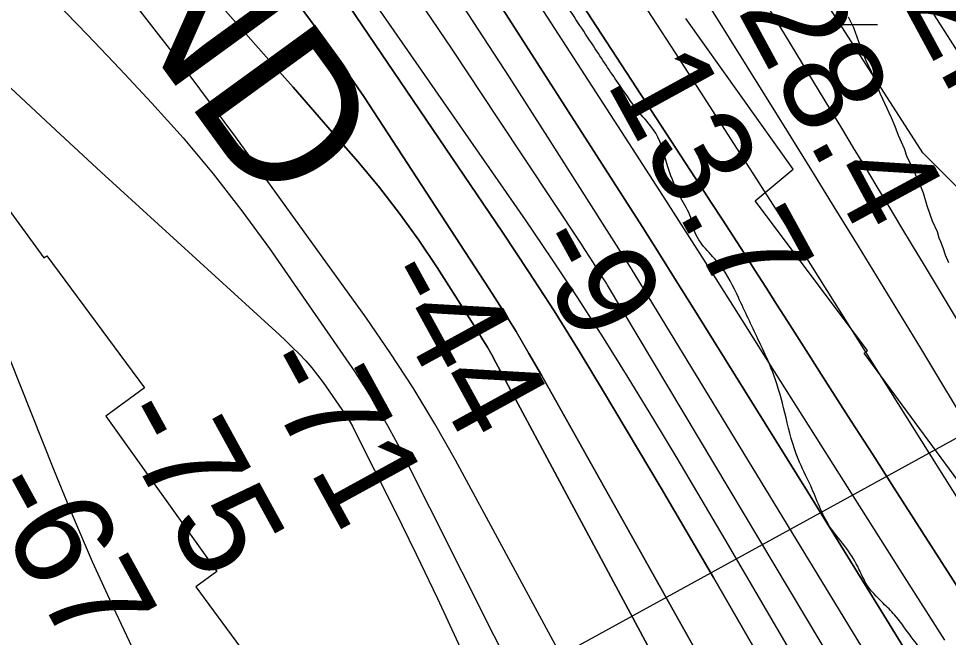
# Model space of a CAD drawing. Extents: x 3329297 to 3367176, y 649250 to 674653.
# Drawn here: x 3341150 to 3341775, y 667097 to 667513 of the extents above; entities that cross this region are included whole.
import ezdxf

# ---------------------------------------------------------------- set-up
doc = ezdxf.new("R2010")
doc.units = 0
for name, color, linetype in [('V-RIVR-EDGE', 7, 'Continuous'), ('V-RIVR-RANG', 7, 'Continuous'), ('V-RRAP-RVMT', 7, 'Continuous'), ('V-RRAP-RVMT-IDEN', 7, 'Continuous'), ('V-SITE-VEGE', 7, 'Continuous'), ('V-TOPO-DPTH', 7, 'Continuous'), ('V-TOPO-MAJR', 7, 'Continuous'), ('V-TOPO-MINR', 7, 'Continuous'), ('V-TOPO-WATR', 7, 'Continuous'), ('V-WETL-SWMP', 7, 'Continuous')]:
    doc.layers.add(name, color=color, linetype=linetype)

msp = doc.modelspace()

# ---------------------------------------------------------------- linework, layer by layer
at = {"layer": 'V-RIVR-EDGE'}
msp.add_spline([(3342816.41, 664076.7), (3342812.76, 664100.73), (3342811.24, 664114.69), (3342810.49, 664125.17), (3342811.67, 664129.43), (3342815.94, 664131.36), (3342822.14, 664130.96), (3342827.58, 664133.66), (3342827.98, 664138.7), (3342825.71, 664163.52), (3342823.01, 664169.35), (3342818.01, 664185.26), (3342816.5, 664200), (3342816.91, 664208.92), (3342818.1, 664220.94), (3342817.34, 664227.14), (3342814.66, 664243.44), (3342809.27, 664257.41), (3342808.51, 664264.01), (3342808.92, 664272.54), (3342814.79, 664296.18), (3342814.82, 664305.49), (3342810.59, 664319.46), (3342799.78, 664338.87), (3342790.88, 664350.14), (3342779.66, 664360.25), (3342778.51, 664365.3), (3342779.3, 664369.17), (3342779.69, 664370.72), (3342785.91, 664376.91), (3342798.35, 664388.13), (3342804.18, 664396.26), (3342807.71, 664410.21), (3342807.34, 664416.8), (3342805.02, 664421.46), (3342805.03, 664424.18), (3342805.05, 664435.04), (3342805.48, 664451.32), (3342803.59, 664468.39), (3342800.14, 664485.46), (3342800.15, 664492.05), (3342800.55, 664495.93), (3342805.6, 664499.41), (3342810.27, 664507.15), (3342811.45, 664513.74), (3342812.65, 664526.54), (3342808.84, 664554.08), (3342808.48, 664564.55), (3342811.98, 664571.52), (3342819.76, 664577.71), (3342825.21, 664588.56), (3342825.62, 664596.7), (3342825.25, 664604.07), (3342821.39, 664610.67), (3342817.54, 664623.86), (3342808.64, 664632.03), (3342807.5, 664639.01), (3342807.51, 664645.61), (3342805.59, 664651.04), (3342795.55, 664667.74), (3342786.28, 664683.28), (3342782.79, 664682.12), (3342779.3, 664685.62), (3342772.36, 664698.82), (3342765.01, 664705.82), (3342757.66, 664715.15), (3342754.96, 664720.97), (3342754.97, 664725.24), (3342756.92, 664729.5), (3342762.36, 664734.91), (3342763.16, 664745.77), (3342759.34, 664768.66), (3342756.66, 664780.69), (3342750.49, 664796.21), (3342738.91, 664818.35), (3342728.88, 664839.31), (3342718.83, 664850.59), (3342704.53, 664870.4), (3342673.21, 664906.93), (3342667.03, 664917.03), (3342662.4, 664928.67), (3342645.77, 664948.1), (3342638.82, 664957.43), (3342632.64, 664969.85), (3342630.72, 664978), (3342626.86, 664984.99), (3342614.87, 664996.66), (3342611.39, 664999.38), (3342609.84, 665001.32), (3342609.85, 665006.36), (3342606.76, 665010.25), (3342597.86, 665020.35), (3342593.22, 665025.41), (3342592.47, 665033.17), (3342590.94, 665044.42), (3342589.42, 665054.5), (3342588.28, 665065.36), (3342585.98, 665077), (3342585.23, 665086.7), (3342585.25, 665096.4), (3342584.88, 665101.05), (3342582.95, 665104.16), (3342580.25, 665109.59), (3342577.16, 665116.97), (3342577.18, 665122.79), (3342577.2, 665131.71), (3342577.22, 665142.56), (3342577.25, 665154.2), (3342576.12, 665167.77), (3342572.7, 665192.99), (3342566.93, 665215.11), (3342563.48, 665229.47), (3342558.85, 665239.95), (3342557.31, 665244.22), (3342555.4, 665255.47), (3342553.11, 665268.66), (3342549.27, 665284.57), (3342541.57, 665307.08), (3342537.34, 665321.83), (3342531.95, 665340.07), (3342533.51, 665343.55), (3342533.53, 665349.76), (3342526.98, 665368.39), (3342525.46, 665379.64), (3342523.54, 665388.18), (3342518.15, 665403.7), (3342515.47, 665416.12), (3342514.34, 665430.86), (3342508.57, 665450.65), (3342503.19, 665470.83), (3342492.38, 665490.63), (3342491.63, 665499.17), (3342490.87, 665508.48), (3342486.28, 665532.92), (3342483.6, 665545.33), (3342477.81, 665557.76), (3342475.93, 665580.26), (3342474.8, 665594.22), (3342470.17, 665605.48), (3342467.87, 665614.4), (3342467.13, 665629.53), (3342466.39, 665643.49), (3342466.82, 665662.1), (3342467.25, 665679.55), (3342463.41, 665695.46), (3342454.93, 665713.71), (3342445.67, 665732.35), (3342448.39, 665735.45), (3342449.55, 665735.05), (3342454.58, 665728.84), (3342456.13, 665730.38), (3342456.13, 665730.77), (3342455.37, 665734.65), (3342442.22, 665750.97), (3342428.7, 665771.56), (3342413.65, 665800.68), (3342398.6, 665832.52), (3342380.47, 665869.41), (3342358.86, 665914.06), (3342350, 665938.51), (3342337.27, 665963.36), (3342312.2, 666021.59), (3342297.17, 666058.47), (3342281.74, 666092.64), (3342274.81, 666112.43), (3342267.5, 666136.11), (3342262.92, 666165.98), (3342261.43, 666190.8), (3342261.45, 666198.56), (3342257.57, 666197.79), (3342255.25, 666199.74), (3342252.93, 666205.17), (3342252.57, 666212.54), (3342252.58, 666219.13), (3342250.29, 666232.71), (3342241.82, 666258.33), (3342236.07, 666285.87), (3342231.81, 666288.99), (3342227.55, 666291.71), (3342219.05, 666302.59), (3342218.67, 666306.86), (3342219.07, 666312.29), (3342210.16, 666314.25), (3342205.13, 666318.91), (3342203.98, 666324.35), (3342203.99, 666330.16), (3342202.08, 666339.09), (3342191.65, 666356.56), (3342180.04, 666369), (3342175.41, 666377.55), (3342164.99, 666396.96), (3342154.58, 666421.81), (3342139.95, 666463.34), (3342130.7, 666487.79), (3342122.99, 666506.43), (3342111.8, 666527.4), (3342098.68, 666554.19), (3342094.83, 666565.83), (3342092.54, 666581.74), (3342088.69, 666594.54), (3342085.25, 666612.78), (3342082.17, 666622.09), (3342072.89, 666631.81), (3342063.22, 666645.41), (3342057.44, 666657.83), (3342049.73, 666678.02), (3342048.22, 666693.14), (3342050.17, 666696.63), (3342050.96, 666704.38), (3342046.71, 666709.05), (3342039.36, 666716.82), (3342032.41, 666729.25), (3342015.81, 666761.09), (3342003.06, 666780.9), (3341996.09, 666786.35), (3341994.95, 666792.55), (3341992.63, 666796.44), (3341982.97, 666811.97), (3341967.13, 666835.28), (3341953.59, 666848.89), (3341946.63, 666857.44), (3341940.45, 666867.92), (3341935.81, 666874.14), (3341919.16, 666884.26), (3341915.69, 666890.09), (3341911.45, 666900.18), (3341899.85, 666913.78), (3341894.82, 666921.16), (3341889.03, 666931.65), (3341869.32, 666956.91), (3341855.01, 666974.78), (3341848.82, 666978.67), (3341839.53, 666986.84), (3341829.09, 667000.44), (3341821.76, 667015.19), (3341819.07, 667024.89), (3341817.15, 667031.1), (3341806.31, 667038.89), (3341788.13, 667056.77), (3341778.46, 667069.98), (3341769.56, 667076.21), (3341762.98, 667079.71), (3341756.02, 667089.04), (3341748.29, 667099.53), (3341738.62, 667112.35), (3341730.89, 667120.12), (3341719.29, 667133.73), (3341714.66, 667143.05), (3341706.55, 667156.64), (3341694.95, 667171.79), (3341682.22, 667198.97), (3341673.73, 667217.22), (3341665.66, 667244.77), (3341658.35, 667270.77), (3341654.5, 667280.86), (3341646.79, 667297.56), (3341633.67, 667325.51), (3341621.31, 667347.26), (3341603.92, 667370.57), (3341601.61, 667379.11), (3341595.05, 667392.31), (3341586.57, 667412.5), (3341578.1, 667435.79), (3341568.43, 667448.22), (3341554.13, 667467.65), (3341537.52, 667492.51), (3341516.66, 667523.97), (3341476.08, 667581.85), (3341429.71, 667650.22), (3341398.03, 667697.22), (3341370.98, 667737.23), (3341354.76, 667763.64), (3341343.55, 667778.41), (3341338.9, 667782.3), (3341332.33, 667790.07), (3341325.39, 667805.99), (3341317.65, 667814.15), (3341305.28, 667827.37), (3341300.64, 667833.19), (3341282.89, 667869.69), (3341259.72, 667911.24), (3341224.58, 667969.5), (3341190.57, 668018.45), (3341159.67, 668067), (3341126.02, 668105.48), (3341085.81, 668151.72), (3341034.77, 668213.12), (3340998.8, 668250.83), (3340967.07, 668282.32), (3340929.92, 668312.66), (3340887.35, 668349.99), (3340852.52, 668378), (3340818.08, 668406.01), (3340783.64, 668439.06), (3340747.67, 668475.99), (3340722.92, 668504.36), (3340704.36, 668525.73), (3340693.92, 668537.01), (3340680.75, 668543.24), (3340672.61, 668546.75), (3340664.48, 668552.59), (3340650.93, 668563.48), (3340645.91, 668568.92), (3340640.88, 668576.69), (3340634.7, 668584.08), (3340619.62, 668601.57), (3340609.54, 668604.69), (3340603.74, 668608.97), (3340599.1, 668614.41), (3340595.62, 668621.01), (3340589.43, 668627.24), (3340567.76, 668645.9), (3340549.95, 668659.13), (3340496.93, 668702.7), (3340430.76, 668760.64), (3340383.93, 668798.76), (3340346.77, 668824.45), (3340316.96, 668845.08), (3340289.86, 668863.37), (3340255.41, 668891.77), (3340209.37, 668936.09), (3340181.13, 668962.92), (3340159.06, 668977.32), (3340134.29, 668996.39), (3340120.75, 669009.22), (3340113.4, 669017.77), (3340109.92, 669023.59), (3340107.6, 669025.92), (3340099.85, 669026.72), (3340094.42, 669027.9), (3340089.39, 669030.24), (3340085.14, 669036.45), (3340084.76, 669043.04), (3340082.06, 669046.15), (3340066.19, 669058.99), (3340051.1, 669071.44), (3340041.8, 669077.66), (3339987.61, 669116.19), (3339929.52, 669149.3), (3339882.28, 669177.34), (3339823.8, 669212), (3339768.82, 669245.87), (3339704.94, 669289.46), (3339659.64, 669320.6), (3339613.98, 669359.49), (3339576.03, 669382.85), (3339562.87, 669392.97), (3339559.39, 669394.53), (3339555.89, 669394.15), (3339553.17, 669389.89), (3339550.84, 669388.73), (3339546.19, 669392.24), (3339540.39, 669395.35), (3339537.28, 669393.03), (3339533.01, 669392.66), (3339518.67, 669398.12), (3339507.83, 669404.74), (3339498.93, 669411.35), (3339490.01, 669411.38), (3339486.53, 669416.04), (3339483.43, 669417.6), (3339473.36, 669420.73), (3339460.58, 669427.74), (3339447.8, 669435.52), (3339435.41, 669443.31), (3339423.8, 669453.42), (3339413.36, 669464.7), (3339407.94, 669471.3), (3339393.62, 669479.48), (3339378.13, 669489.21), (3339357.61, 669502.45), (3339355.67, 669504.78), (3339358.39, 669506.33), (3339359.56, 669509.43), (3339359.18, 669510.98), (3339356.48, 669515.25), (3339347.17, 669516.82), (3339341.34, 669512.57), (3339338.24, 669513.36), (3339320.82, 669525.81), (3339311.15, 669534.75), (3339296.06, 669548.75), (3339293.35, 669550.31), (3339286.37, 669549.16), (3339280.93, 669546.46), (3339277.05, 669546.47), (3339268.14, 669549.98), (3339250.71, 669559.72), (3339229.04, 669575.67), (3339210.84, 669586.97), (3339202.33, 669595.13), (3339200.4, 669599.4), (3339200.02, 669604.83), (3339198.1, 669611.04), (3339183.01, 669622.71), (3339166.35, 669632.45)], degree=3, dxfattribs=at)
at = {"layer": 'V-RIVR-RANG'}
msp.add_line((3342064.84, 667387.2), (3341170.56, 666896.62), dxfattribs=at)
at = {"layer": 'V-RRAP-RVMT'}
for p, q in [((3341670.53, 667411.57), (3341598.25, 667512.81)), ((3341091.32, 667456.13), (3341167.14, 667352.04)), ((3341645.03, 667390.4), (3341670.53, 667411.57)), ((3341720.37, 667289.92), (3341645.03, 667390.4)), ((3341167.14, 667352.04), (3341169.19, 667353.5)), ((3341169.19, 667353.5), (3341234.74, 667264.88)), ((3341718.22, 667288.14), (3341720.37, 667289.92)), ((3341784.24, 667198.22), (3341718.22, 667288.14)), ((3341234.74, 667264.88), (3341208.65, 667245.72)), ((3341208.65, 667245.72), (3341283.36, 667141.46)), ((3341283.36, 667141.46), (3341269.18, 667131.22)), ((3341269.18, 667131.22), (3341343.79, 667030.34))]:
    msp.add_line(p, q, dxfattribs=at)
at = {"layer": 'V-SITE-VEGE'}
msp.add_lwpolyline([(3341775, 667348.85), (3341772.7, 667354.01), (3341771.49, 667358.17), (3341769.73, 667362.83), (3341768.58, 667365.41), (3341767.37, 667369.57), (3341763.94, 667376.79), (3341760.39, 667387.16), (3341757.97, 667395.47), (3341755.65, 667401.16), (3341749.89, 667414.06), (3341747.05, 667419.73), (3341745.25, 667425.44), (3341741.24, 667434.22), (3341738.9, 667440.43), (3341736.58, 667446.12), (3341729.13, 667462.12), (3341722.75, 667477.63), (3341719.91, 667483.3), (3341717.58, 667488.98), (3341714.64, 667497.28), (3341711.13, 667506.6), (3341707.7, 667513.82)], dxfattribs=at)
at = {"layer": 'V-TOPO-DPTH'}
for points in [[(3341137.76, 668102.82), (3341154.48, 668083.17), (3341170.75, 668063.13), (3341186.41, 668042.6), (3341201.7, 668021.8), (3341216.45, 668000.62), (3341230.84, 667979.17), (3341608.08, 667400.76), (3341615.47, 667389.4), (3341622.83, 667378.02), (3341630.16, 667366.62), (3341637.47, 667355.21), (3341644.76, 667343.78), (3341652.06, 667332.36), (3341659.35, 667320.93), (3341666.65, 667309.51), (3341680.77, 667287.39), (3341695.13, 667264.91), (3341709.51, 667242.44), (3341723.89, 667219.98), (3341738.29, 667197.52), (3341908.11, 666932.71)], [(3341104.06, 668055.41), (3341257.64, 667840.64), (3341313.58, 667761.14), (3341368.7, 667681.08), (3341422.6, 667600.2), (3341475.68, 667518.75), (3341557.41, 667391.26), (3341568.97, 667373.13), (3341580.49, 667354.96), (3341591.93, 667336.75), (3341603.33, 667318.5), (3341679.99, 667195.14), (3341729.48, 667115.07), (3341778.71, 667034.84)], [(3341778.71, 667034.84), (3341729.48, 667115.07), (3341679.99, 667195.14), (3341603.33, 667318.5), (3341591.93, 667336.75), (3341580.49, 667354.96), (3341568.97, 667373.13), (3341557.41, 667391.26), (3341475.68, 667518.75), (3341422.6, 667600.2), (3341368.7, 667681.08), (3341313.58, 667761.14), (3341257.64, 667840.64), (3341104.06, 668055.41)], [(3341871.92, 666787.71), (3341545.81, 667333.66), (3341545.26, 667334.57), (3341544.14, 667336.39), (3341543.58, 667337.3), (3341539.12, 667344.4), (3341536.3, 667348.84), (3341533.47, 667353.27), (3341530.6, 667357.68), (3341527.71, 667362.08), (3341472.13, 667445.97), (3341441.3, 667492.21), (3341410.31, 667538.34), (3341379.07, 667584.31), (3341347.66, 667630.15), (3341163.74, 667897.04), (3341145.35, 667922.71)], [(3341871.92, 666787.71), (3341545.81, 667333.66), (3341545.26, 667334.57), (3341544.14, 667336.39), (3341543.58, 667337.3), (3341539.12, 667344.4), (3341536.3, 667348.84), (3341533.47, 667353.27), (3341530.6, 667357.68), (3341527.71, 667362.08), (3341472.13, 667445.97), (3341441.3, 667492.21), (3341410.31, 667538.34), (3341379.07, 667584.31), (3341347.66, 667630.15), (3341163.74, 667897.04), (3341145.35, 667922.71)], [(3341083.52, 667870.17), (3341157.79, 667794.75), (3341202.82, 667746.46), (3341246, 667696.64), (3341286.4, 667644.54), (3341324.94, 667590.92), (3341475.12, 667369.46), (3341492.67, 667343.06), (3341509.91, 667316.46), (3341526.65, 667289.55), (3341543.08, 667262.43), (3341581.71, 667197.34), (3341616.91, 667137.35), (3341651.73, 667077.14), (3341685.95, 667016.6), (3341719.79, 666955.83), (3341928.37, 666576.87), (3341943.16, 666549.3), (3341957.55, 666521.53), (3341971.34, 666493.45), (3341984.73, 666465.17), (3342014.48, 666400.56), (3342041.88, 666339.59), (3342068.54, 666278.3)], [(3342068.54, 666278.3), (3342041.88, 666339.59), (3342014.48, 666400.56), (3341984.73, 666465.17), (3341971.34, 666493.45), (3341957.55, 666521.53), (3341943.16, 666549.3), (3341928.37, 666576.87), (3341719.79, 666955.83), (3341685.95, 667016.6), (3341651.73, 667077.14), (3341616.91, 667137.35), (3341581.71, 667197.34), (3341543.08, 667262.43), (3341526.65, 667289.55), (3341509.91, 667316.46), (3341492.67, 667343.06), (3341475.12, 667369.46), (3341324.94, 667590.92), (3341286.4, 667644.54), (3341246, 667696.64), (3341202.82, 667746.46), (3341157.79, 667794.75), (3341083.52, 667870.17)], [(3341144.15, 667741.81), (3341170.77, 667713.11), (3341197.37, 667684.39), (3341223.95, 667655.65), (3341250.5, 667626.89), (3341263.23, 667613.09), (3341295.18, 667576.66), (3341325.84, 667539.24), (3341354.6, 667500.33), (3341382.07, 667460.43), (3341466.29, 667331.31), (3341475.41, 667317), (3341484.34, 667302.58), (3341492.98, 667287.98), (3341501.42, 667273.26), (3341716.55, 666889.35)], [(3341144.15, 667741.81), (3341170.77, 667713.11), (3341197.37, 667684.39), (3341223.95, 667655.65), (3341250.5, 667626.89), (3341263.23, 667613.09), (3341295.18, 667576.66), (3341325.84, 667539.24), (3341354.6, 667500.33), (3341382.07, 667460.43), (3341466.29, 667331.31), (3341475.41, 667317), (3341484.34, 667302.58), (3341492.98, 667287.98), (3341501.42, 667273.26), (3341716.55, 666889.35)], [(3341623.65, 666996.78), (3341470.8, 667281.93), (3341467.98, 667287.05), (3341465.09, 667292.12), (3341462.08, 667297.12), (3341459, 667302.08), (3341431.31, 667345.53), (3341418.98, 667363.96), (3341406.12, 667382.01), (3341392.48, 667399.46), (3341378.32, 667416.52), (3341363.74, 667433.28), (3341349.13, 667450), (3341334.48, 667466.7), (3341319.81, 667483.37), (3341251.54, 667560.74), (3341202.86, 667616.2), (3341154.38, 667671.85), (3341106.21, 667727.75)], [(3341106.21, 667727.75), (3341154.38, 667671.85), (3341202.86, 667616.2), (3341251.54, 667560.74), (3341319.81, 667483.37), (3341334.48, 667466.7), (3341349.13, 667450), (3341363.74, 667433.28), (3341378.32, 667416.52), (3341392.48, 667399.46), (3341406.12, 667382.01), (3341418.98, 667363.96), (3341431.31, 667345.53), (3341459, 667302.08), (3341462.08, 667297.12), (3341465.09, 667292.12), (3341467.98, 667287.05), (3341470.8, 667281.93), (3341623.65, 666996.78)]]:
    msp.add_lwpolyline(points, dxfattribs=at)
at = {"layer": 'V-TOPO-MAJR'}
for points in [[(3341926.28, 667072.72), (3341895.15, 667122.52), (3341864.24, 667172.44), (3341833.64, 667222.55), (3341803.25, 667272.79), (3341758.6, 667347.14), (3341750.69, 667360.31), (3341742.78, 667373.47), (3341734.86, 667386.63), (3341726.94, 667399.78), (3341719.01, 667412.93), (3341711.07, 667426.08), (3341703.12, 667439.22), (3341695.17, 667452.35), (3341635.54, 667550.75), (3341597.7, 667613.04), (3341559.78, 667675.29), (3341521.74, 667737.46), (3341483.62, 667799.58), (3341259.17, 668164.54)], [(3342186.27, 665545.24), (3341820.92, 666452.1), (3341819.26, 666456.15), (3341817.57, 666460.18), (3341815.83, 666464.18), (3341814.06, 666468.18), (3341728.93, 666656.73), (3341683.52, 666754.47), (3341636.71, 666851.51), (3341587.81, 666947.52), (3341537.51, 667042.83), (3341443.59, 667216.2), (3341429.7, 667240.71), (3341415.2, 667264.83), (3341399.78, 667288.38), (3341383.75, 667311.54), (3341296.04, 667433.19), (3341256.2, 667486.76), (3341215.34, 667539.52), (3341172.95, 667591.05), (3341129.52, 667641.76)]]:
    msp.add_lwpolyline(points, dxfattribs=at)
at = {"layer": 'V-TOPO-MINR'}
for points in [[(3342189.2, 666175.28), (3342141.23, 666287.97), (3342040.66, 666518.34), (3342033.16, 666534.89), (3342025.36, 666551.3), (3342017.11, 666567.49), (3342008.57, 666583.53), (3341936.91, 666713.67), (3341891.79, 666794.37), (3341845.96, 666874.66), (3341799.07, 666954.33), (3341751.48, 667033.6), (3341573.07, 667326.35), (3341567.42, 667335.56), (3341561.74, 667344.76), (3341556.01, 667353.92), (3341550.24, 667363.06), (3341507.31, 667430.69), (3341479.84, 667473.49), (3341452.09, 667516.11), (3341423.93, 667558.46), (3341395.49, 667600.63), (3341082.73, 668059.45), (3340316.23, 668769.41)], [(3341895.67, 667048.62), (3341861.97, 667109.98), (3341827.59, 667170.96), (3341792.22, 667231.36), (3341756.19, 667291.39), (3341714.28, 667359.9), (3341698.67, 667385.36), (3341683.01, 667410.79), (3341667.28, 667436.18), (3341651.52, 667461.54), (3341429.29, 667818.02), (3341393.68, 667873.84), (3341357.31, 667929.15), (3341319.79, 667983.68), (3341281.52, 668037.7), (3341236.49, 668099.86), (3341219.72, 668122.06), (3341202.38, 668143.78), (3341184.18, 668164.78), (3341165.41, 668185.31), (3341017.82, 668340.33)], [(3341847.41, 667082.78), (3341788.64, 667178.34), (3341666.37, 667372.96), (3341659.62, 667383.67), (3341652.84, 667394.37), (3341646.03, 667405.04), (3341639.2, 667415.7), (3341591.49, 667489.89), (3341560.61, 667537.52), (3341529.49, 667585), (3341498.02, 667632.23), (3341466.31, 667679.32), (3341172.62, 668111.86), (3341169.37, 668116.46), (3341166.02, 668120.98), (3341162.51, 668125.37), (3341158.89, 668129.68), (3341119.39, 668175.02)], [(3341908.11, 666932.71), (3341738.29, 667197.52), (3341723.89, 667219.98), (3341709.51, 667242.44), (3341695.13, 667264.91), (3341680.77, 667287.39), (3341666.65, 667309.51), (3341659.35, 667320.93), (3341652.06, 667332.36), (3341644.76, 667343.78), (3341637.47, 667355.21), (3341630.16, 667366.62), (3341622.83, 667378.02), (3341615.47, 667389.4), (3341608.08, 667400.76), (3341230.84, 667979.17), (3341216.45, 668000.62), (3341201.7, 668021.8), (3341186.41, 668042.6), (3341170.75, 668063.13), (3341154.48, 668083.17), (3341137.76, 668102.82)], [(3341707.98, 667814.24), (3341827.04, 667537.96), (3341835.24, 667518.11), (3341843.03, 667498.11), (3341850.2, 667477.89), (3341856.97, 667457.51), (3341889.76, 667353.54), (3341888.21, 667347.19), (3341885.4, 667343.42), (3341880.7, 667343.55), (3341874.75, 667346.27), (3341868.19, 667355.91), (3341855.43, 667374.88), (3341842.8, 667393.93), (3341830.35, 667413.11), (3341818.03, 667432.37), (3341805.79, 667451.68), (3341793.53, 667470.98), (3341781.24, 667490.26), (3341768.93, 667509.52), (3341397.03, 668090.56)], [(3341772.26, 667095.37), (3341743.64, 667140.45), (3341715.05, 667185.55), (3341686.5, 667230.67), (3341657.99, 667275.82), (3341636.34, 667310.13), (3341618.62, 667338.11), (3341600.85, 667366.04), (3341582.97, 667393.92), (3341565.04, 667421.75), (3341367.16, 667727.7), (3341326.65, 667788.95), (3341285.32, 667849.64), (3341242.75, 667909.46), (3341199.37, 667968.72), (3341139.07, 668049.33)], [(3341871.92, 666787.71), (3341545.81, 667333.66), (3341545.26, 667334.57), (3341544.14, 667336.39), (3341543.58, 667337.3), (3341539.12, 667344.4), (3341536.3, 667348.84), (3341533.47, 667353.27), (3341530.6, 667357.68), (3341527.71, 667362.08), (3341472.13, 667445.97), (3341441.3, 667492.21), (3341410.31, 667538.34), (3341379.07, 667584.31), (3341347.66, 667630.15), (3341163.74, 667897.04), (3341145.35, 667922.71)], [(3342349.38, 665627.96), (3341997.45, 666523), (3341996.52, 666525.28), (3341994.55, 666529.78), (3341992.4, 666534.2), (3341990.08, 666538.53), (3341988.86, 666540.67), (3341624.77, 667163.06), (3341608.7, 667190.33), (3341592.53, 667217.53), (3341576.18, 667244.64), (3341559.72, 667271.67), (3341542.96, 667298.51), (3341525.89, 667325.16), (3341508.37, 667351.51), (3341490.55, 667377.66), (3341294.34, 667660.4), (3341251.32, 667718.78), (3341206.22, 667775.4), (3341157.99, 667829.37), (3341107.66, 667881.58)], [(3342068.54, 666278.3), (3342041.88, 666339.59), (3342014.48, 666400.56), (3341984.73, 666465.17), (3341971.34, 666493.45), (3341957.55, 666521.53), (3341943.16, 666549.3), (3341928.37, 666576.87), (3341719.79, 666955.83), (3341685.95, 667016.6), (3341651.73, 667077.14), (3341616.91, 667137.35), (3341581.71, 667197.34), (3341543.08, 667262.43), (3341526.65, 667289.55), (3341509.91, 667316.46), (3341492.67, 667343.06), (3341475.12, 667369.46), (3341324.94, 667590.92), (3341286.4, 667644.54), (3341246, 667696.64), (3341202.82, 667746.46), (3341157.79, 667794.75), (3341083.52, 667870.17)], [(3341716.55, 666889.35), (3341501.42, 667273.26), (3341492.98, 667287.98), (3341484.34, 667302.58), (3341475.41, 667317), (3341466.29, 667331.31), (3341382.07, 667460.43), (3341354.6, 667500.33), (3341325.84, 667539.24), (3341295.18, 667576.66), (3341263.23, 667613.09), (3341250.5, 667626.89), (3341223.95, 667655.65), (3341197.37, 667684.39), (3341170.77, 667713.11), (3341144.15, 667741.81)], [(3341623.65, 666996.78), (3341470.8, 667281.93), (3341467.98, 667287.05), (3341465.09, 667292.12), (3341462.08, 667297.12), (3341459, 667302.08), (3341431.31, 667345.53), (3341418.98, 667363.96), (3341406.12, 667382.01), (3341392.48, 667399.46), (3341378.32, 667416.52), (3341363.74, 667433.28), (3341349.13, 667450), (3341334.48, 667466.7), (3341319.81, 667483.37), (3341251.54, 667560.74), (3341202.86, 667616.2), (3341154.38, 667671.85), (3341106.21, 667727.75)], [(3341125.55, 667574.86), (3341152.59, 667547.16), (3341174.53, 667524.55), (3341196.36, 667501.85), (3341218.06, 667479.01), (3341239.67, 667456.09), (3341260.66, 667432.66), (3341280.93, 667408.65), (3341300.12, 667383.77), (3341318.59, 667358.31), (3341375.91, 667275.48), (3341383.68, 667263.74), (3341391.11, 667251.8), (3341398.03, 667239.56), (3341404.61, 667227.11), (3341576.98, 666884.12)], [(3341628.34, 666143.4), (3341567.07, 666322.07), (3341562.71, 666334.26), (3341558.14, 666346.38), (3341553.26, 666358.37), (3341548.18, 666370.29), (3341284.99, 666964.92), (3341271.21, 666995.61), (3341257.19, 667026.18), (3341242.83, 667056.59), (3341228.24, 667086.9), (3341213.83, 667117.28), (3341199.88, 667147.87), (3341186.63, 667178.77), (3341173.84, 667209.87), (3341056.33, 667505.07)], [(3341144.69, 667466.22), (3341175.05, 667437.8), (3341205.64, 667409.61), (3341320.56, 667304.92), (3341325.17, 667300.66), (3341329.74, 667296.35), (3341334.24, 667291.97), (3341338.7, 667287.55), (3341343, 667282.99), (3341347.13, 667278.29), (3341351.01, 667273.37), (3341354.71, 667268.32), (3341369.23, 667247.34), (3341371.03, 667244.61), (3341372.76, 667241.84)], [(3341372.76, 667241.84), (3341374.37, 667238.99), (3341375.89, 667236.1), (3341402.66, 667182.8), (3341417.28, 667153.11), (3341431.61, 667123.29), (3341445.48, 667093.25), (3341459.05, 667063.07), (3341730.13, 666447.9), (3341734.86, 666437.05), (3341739.53, 666426.17), (3341744.12, 666415.26), (3341748.65, 666404.32), (3341992.02, 665809.99)]]:
    msp.add_lwpolyline(points, dxfattribs=at)
at = {"layer": 'V-TOPO-WATR'}
msp.add_lwpolyline([(3341778.71, 667034.84), (3341729.48, 667115.07), (3341679.99, 667195.14), (3341603.33, 667318.5), (3341591.93, 667336.75), (3341580.49, 667354.96), (3341568.97, 667373.13), (3341557.41, 667391.26), (3341475.68, 667518.75), (3341422.6, 667600.2), (3341368.7, 667681.08), (3341313.58, 667761.14), (3341257.64, 667840.64), (3341104.06, 668055.41)], dxfattribs=at)
at = {"layer": 'V-WETL-SWMP'}
for p, q in [((3341757.53, 667422.57), (3341695.46, 667519.14)), ((3341702.13, 667508.76), (3341727.09, 667508.81)), ((3341812.72, 667367.39), (3341757.53, 667422.57))]:
    msp.add_line(p, q, dxfattribs=at)

# ---------------------------------------------------------------- texts
at = {"layer": 'V-RIVR-RANG'}
for s, rotation, p in [('32.6', 298.42833, (3341719.46, 667568.01)), ('28.4', 298.42833, (3341632.52, 667518.56)), ('13.7', 298.71311, (3341544.26, 667470.3)), ('-9', 298.71311, (3341489.89, 667361.4)), ('-44', 298.71311, (3341388.13, 667339.03)), ('-71', 298.71311, (3341306.64, 667279.63)), ('-75', 298.71311, (3341211.34, 667245.46)), ('-67', 298.71311, (3341124.4, 667196.02))]:
    msp.add_text(s, height=67, rotation=rotation, dxfattribs=at).set_placement(p)
at = {"layer": 'V-RRAP-RVMT-IDEN'}
msp.add_text('BEND', height=100, rotation=306.01525, dxfattribs=at).set_placement((3341100.34, 667681.21))

doc.saveas('drawing.dxf')
